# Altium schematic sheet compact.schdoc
size 292 x 204 mm; Device: A_A4; Symbol: A_A4; Name: A_A4; @Project Name: Roborock fan driver with tacho frequency divider; REV: 1.0; Date: 2024-04-24; Sheet: 1/1; Draw By: David Buezas; Company: Your Company; Convert to PCB: yes; Add into BOM: yes; @Page No: 1; @Page Count: 1; @Schematic Name: Schematic_1; @Board Name: Compact rectangular; @Update Date: 2025-03-14; @Create Time: 20:00:56; @Update Time: 14:11:29; @Page Name: compact; @Create Date: 2025-03-12
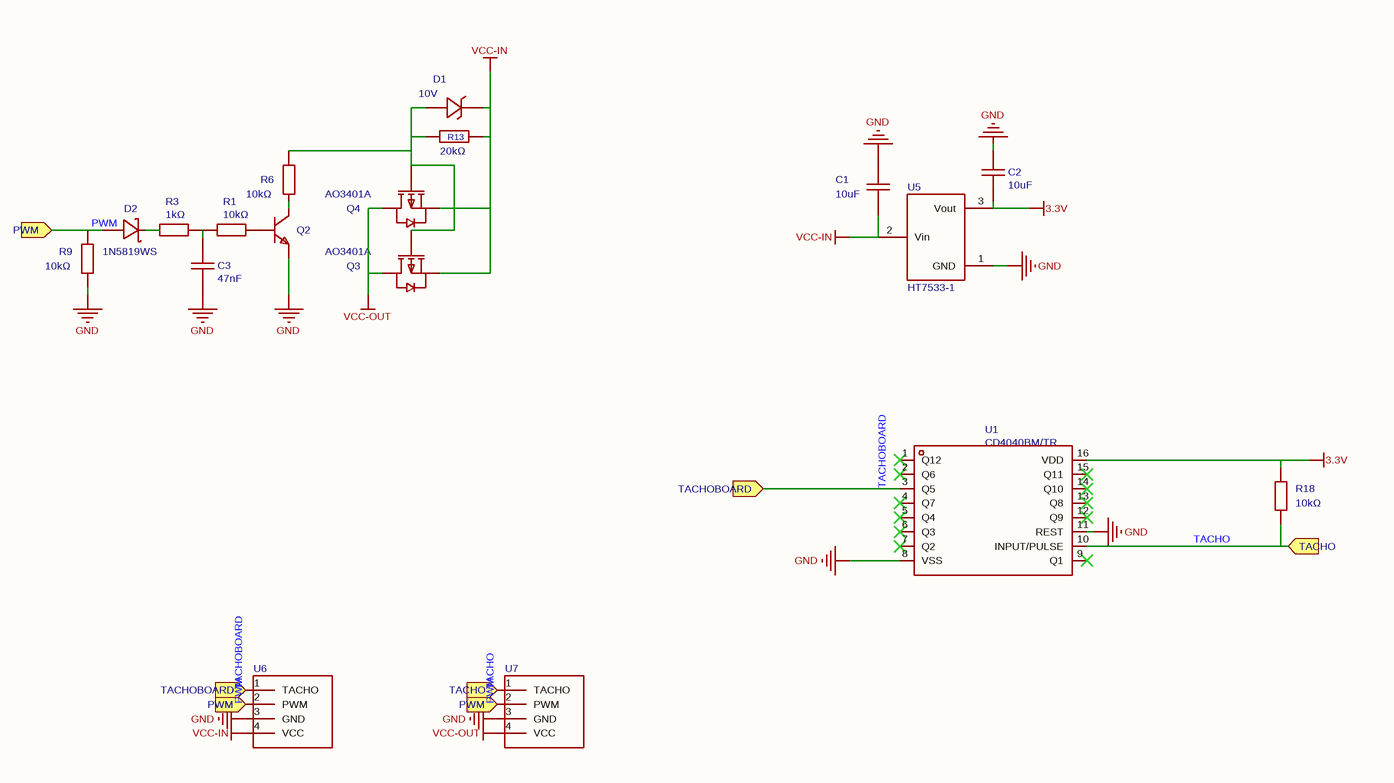
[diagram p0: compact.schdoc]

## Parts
C1  10uF  [C0805]
C2  10uF  [C0603]
C3  47nF  [C0603]
D1  Zener Voltage(Nom): 10V  [SOD-123_L2.7-W1.6-LS3.7-RD]  (hidden comment: MMSZ5240B)
D2  1N5819WS  [SOD-323_L1.8-W1.3-LS2.5-RD]
Q2  SS8050(RANGE:200-350)  [SOT-23-3_L2.9-W1.3-P1.90-LS2.4-BR]  (value not drawn)
Q3  AO3401A  [SOT-23_L2.9-W1.3-P1.90-LS2.4-BR]
Q4  AO3401A  [SOT-23_L2.9-W1.3-P1.90-LS2.4-BR]
R1  10kΩ  [R0603]
R3  1kΩ  [R0603]
R6  10kΩ  [R0603]
R9  10kΩ  [R0603]
R13  20kΩ  [R0603]
R18  10kΩ  [R0603]
U1  CD4040BM/TR  [SOP-16_L9.9-W3.9-P1.27-LS6.0-BL]
U5  HT7533-1  [SOT-89-3_L4.5-W2.5-P1.50-LS4.2-BR]
U6  (no value)  [4P solder pads]
U7  (no value)  [4P solder pads]

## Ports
PWM (in), TACHO (in), TACHOBOARD (in)

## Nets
3.3V: C2.1 R18.2 U1.16(VDD) U5.3(Vout)
GND: C1.2 C2.2 C3.1 Q2.2(E) R9.1 U1.8(VSS) U1.11(REST) U5.1(GND) U6.3(GND) U7.3(GND)
VCC-IN: C1.1 D1.1(K) Q3.2(S) Q4.2(S) R13.2 U5.2(Vin) U6.4(VCC)
VCC-OUT: Q3.3(D) Q4.3(D) U7.4(VCC)
PWM: D2.2(A) R9.2 U6.2(PWM) U7.2(PWM) ; port PWM
TACHO: R18.1 U1.10(INPUT/PULSE) U7.1(TACHO) ; port TACHO
TACHOBOARD: U1.3(Q5) U6.1(TACHO) ; port TACHOBOARD
NetC3_2: C3.2 R1.1 R3.2
NetD1_2: D1.2(A) Q3.1(G) Q4.1(G) R6.2 R13.1
NetD2_1: D2.1(K) R3.1
NetQ2_1: Q2.1(B) R1.2
NetQ2_3: Q2.3(C) R6.1

Not connected (* = marked no-connect by the designer): U1 1(Q12)* 2(Q6)* 4(Q7)* 5(Q4)* 6(Q3)* 7(Q2)* 9(Q1)* 12(Q9)* 13(Q8)* 14(Q10)* 15(Q11)*

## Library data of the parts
C1 = GRM21BR61H106KE43L: Capacitance: Tolerance:±10% Tolerance:±10% Voltage Rated: Temperature Coefficient:; Manufacturer: muRata(村田); Symbol: CL10A105KB8NNNC; Convert to PCB: yes; ModelId: 8c88e81f49c6409b980720ec8953afb6; ModelName: C0805_L2.0-W1.3-H1.3; ModelTransform: 78.74,51.181,0,0,0,0,0,0.0005,0; Tolerance: ±10%
C2 = CL10A106KP8NNNC: Capacitance: Tolerance:±10% Tolerance:±10% Voltage Rated: Temperature Coefficient:; Manufacturer: SAMSUNG(三星); Symbol: CL05A105KA5NQNC; Convert to PCB: yes; ModelId: 624118aa3cc7497086c383c2d72e0852; ModelName: C0603_L1.6-W0.8-H0.8; ModelTransform: 62.992,31.496,0,0,0,0,0,0,0; Tolerance: ±10%
C3 = CL10B473KB8NNNC: Capacitance: Tolerance:±10% Tolerance:±10% Voltage Rated: Temperature Coefficient:; Manufacturer: SAMSUNG(三星); Symbol: CL05A105KA5NQNC; Convert to PCB: yes; ModelId: 624118aa3cc7497086c383c2d72e0852; ModelName: C0603_L1.6-W0.8-H0.8; ModelTransform: 62.992,31.496,0,0,0,0,0,0,0; Tolerance: ±10%
D1 = MMSZ5240B_C19077425: Diode Configuration:Independent Type Zener Voltage(Nom):10V Reverse Leakage Current (Ir):3uA@8V Zener Voltage(Range):9.5V~10.5V Zener Voltage(Range):9.5V~10.5V Pd - Power Dissipation(Pd):500mW Impedance(Zzt):17Ω; Manufacturer: 宏嘉诚; Convert to PCB: yes; ModelId: 31ae3d5c025440ebafdeabfabec0ebeb; ModelName: SOD-123_L2.7-W1.6-H1.4-LS3.7; ModelTransform: 146.026,62.992,0,180,0,0,0.0005,0,0; Reverse Leakage Current (Ir): 3uA@8V; Pd - Power Dissipation(Pd): 500mW; Impedance(Zzt): 17Ω
D2 = 1N5819WS_C191023: Forward Voltage (Vf@If):600mV@1A Reverse Voltage (Vr):40V Rectified Current:1A; Manufacturer: Hottech(合科泰); Convert to PCB: yes; ModelId: 7a4b9b6e725448df9ee2451185154c27; ModelName: SOD-323_L1.7-W1.3-H1.1-LS2.5; ModelTransform: 98.91933,51.181,0,180,0,0,0.985,-0.0005,0; Reverse Voltage (Vr): 40V; Rectified Current: 1A
Q2 = SS8050(RANGE:200-350)_C2150: Transistor Type: Collector Current (Ic): Collector-Emitter Breakdown Voltage (Vceo): Power Dissipation (Pd): DC Current Gain (hFE@Ic,Vce):200@800mA,1V DC Current Gain (hFE@Ic,Vce):200@800mA,1V Transition Frequency (fT):100MHz Collector Cut-Off Current (Ic; Manufacturer: CJ(江苏长电/长晶); Symbol: SS8050_C2150; Convert to PCB: yes; ModelId: 62a57c6760504a01965db6419a6d07df; ModelName: SOT-23-3P_L2.9-W1.3-H1.0-LS2.4-P0.95; ModelTransform: 98.425,114.173,0,180,0,0,0.0005,-0.0005,0; Transition Frequency (fT): 100MHz; Collector Cut-Off Current (Icbo): 100nA; Collector-Emitter Saturation Voltage (VCE(sat)@Ic,Ib): 500mV@800mA,80mA
Q3 Q4 = AO3401A_C15127: Type:1 Piece P-Channel Drain Source Voltage (Vdss): Continuous Drain Current (Id): Drain Source On Resistance (RDS(on)@Vgs,Id):44mΩ@10V,4.3A Power Dissipation (Pd): Gate Threshold Voltage (Vgs(th)@Id):1.3V@250uA Total Gate Charge (Qg@Vgs):12.2nC@4.5V Inpu; Manufacturer: AOS; AddInBom: yes; ModelId: 62a57c6760504a01965db6419a6d07df; ModelName: SOT-23-3P_L2.9-W1.3-H1.0-LS2.4-P0.95; ModelTransform: 98.64468,114.173,0,180,0,0,0,0,0; Input Capacitance (Ciss@Vds): 1.2nF@15V
R1 R6 R9 R18 = 0603WAF1002T5E: Type:Thick Film Resistors Resistance:10kΩ Tolerance:±1% Tolerance:±1% Power(Watts): Overload Voltage (Max): Temperature Coefficient:±100ppm/℃ Temperature Coefficient:±100ppm/℃ Operating Temperature Range:-55℃~+155℃ Operating Temperature Range:-55℃~+155℃; Manufacturer: UNI-ROYAL(厚声); Convert to PCB: yes; ModelId: 112863783b5b41f1b5254f87eedc7932; ModelTransform: 31.8897,63.7794,0,90,0,0,0,0,0; Tolerance: ±1%
R3 = 0603WAF1001T5E: Type:Thick Film Resistors Resistance:1kΩ Tolerance:±1% Tolerance:±1% Power(Watts): Overload Voltage (Max): Temperature Coefficient:±100ppm/℃ Temperature Coefficient:±100ppm/℃ Operating Temperature Range:-55℃~+155℃ Operating Temperature Range:-55℃~+155℃; Manufacturer: UNI-ROYAL(厚声); Convert to PCB: yes; ModelId: 112863783b5b41f1b5254f87eedc7932; ModelTransform: 31.8897,63.7794,0,90,0,0,0,0,0; Tolerance: ±1%
R13 = 0603WAF2002T5E: Type:Thick Film Resistors Resistance:20kΩ Tolerance:±1% Tolerance:±1% Power(Watts): Overload Voltage (Max): Temperature Coefficient:±100ppm/℃ Temperature Coefficient:±100ppm/℃ Operating Temperature Range:-55℃~+155℃ Operating Temperature Range:-55℃~+155℃; Manufacturer: UNI-ROYAL(厚声); AddInBom: yes; ModelId: 112863783b5b41f1b5254f87eedc7932; ModelTransform: 31.8897,63.7794,0,90,0,0,0,0,0; Tolerance: ±1%
U1 = CD4040BM/TR: Manufacturer: HGSEMI(华冠); Convert to PCB: yes; ModelId: 2f91ac34cbab4a3da9c51136f871f91e; ModelTransform: 389.763,236.22,0,0,0,0,0,0,0
U5 = HT7533-1_C14289: Output Type:Fixed Voltage - Supply:30V Output Voltage:3.3V Output Voltage:3.3V Output Current:100mA Power Supply Rejection Ratio (PSRR):- Voltage Dropout:55mV@(1mA) standby current:- Output Configuration:Positive electrode Number of Outputs:1; Manufacturer: HOLTEK(合泰/盛群); Convert to PCB: yes; ModelId: 78d1c457a54a48a6982859ae8b9fc42d; ModelName: SOT-89-3_L4.3-W2.5-H1.6-LS4.1-P1.50; ModelTransform: 161.417,169.291,0,180,0,0,-11.808,0,0; Output Type: Fixed; Voltage - Supply: 30V; Output Voltage: 3.3V; Output Current: 100mA; Number of Outputs: 1
U6 U7 = 4P solder pads: AddInBom: no; ConvertToPcb: yes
